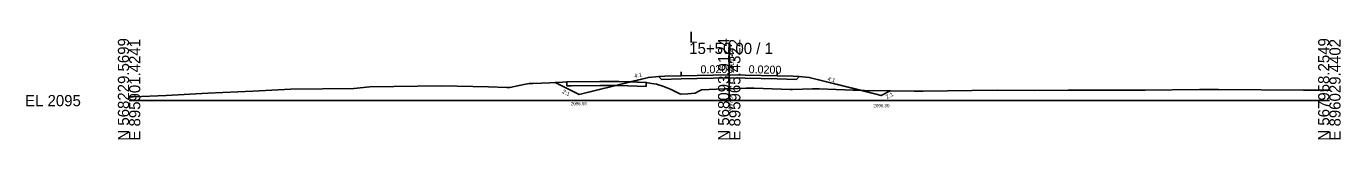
# Model space of a CAD drawing. Extents: x -26 to 1603, y -10 to 13527.
# Drawn here: x -25.7 to 302.8, y 2990.3 to 3017.2 of the extents above; entities that cross this region are included whole.
import ezdxf

# ---------------------------------------------------------------- set-up
doc = ezdxf.new("R2010")
doc.units = 0
for name, color, linetype in [('Default', 7, 'Continuous'), ('Exist XS Center Line Elevation Label', 7, 'Continuous'), ('Exist XS Ground Line', 7, 'Continuous'), ('Old_Level_61', 7, 'Continuous'), ('Old_Level_63', 7, 'Continuous'), ('Prop XS Ditch Slope Text', 7, 'Continuous'), ('Prop XS Ditch Standard Text', 7, 'Continuous'), ('Prop XS Earthwork Shape', 7, 'Continuous'), ('Prop XS EOT Tick Mark', 7, 'Continuous'), ('Prop XS Finish Grade', 7, 'Continuous'), ('Prop XS Finish Grade Earthwork', 7, 'Continuous'), ('Prop XS Finish Grade Paved Shoulder', 7, 'Continuous'), ('Prop XS Finish Grade Pavement', 7, 'Continuous'), ('Prop XS Side Slope Text', 7, 'Continuous'), ('Prop XS Subgrade Earthwork', 7, 'Continuous'), ('Prop XSC Text', 7, 'Continuous')]:
    doc.layers.add(name, color=color, linetype=linetype)

msp = doc.modelspace()

# ---------------------------------------------------------------- linework, layer by layer
at = {"layer": 'Exist XS Ground Line'}
for p, q in [((30.97, 3002.33), (40.4, 3002.86)), ((40.4, 3002.86), (56.16, 3003.06)), ((56.16, 3003.06), (60.17, 3003.41)), ((60.17, 3003.41), (78.12, 3003.66)), ((78.12, 3003.66), (89.84, 3003.44)), ((89.84, 3003.44), (94.43, 3003.24)), ((94.43, 3003.24), (95.17, 3003.27)), ((95.17, 3003.27), (98.7, 3004.04)), ((98.7, 3004.04), (99.98, 3004.25)), ((99.98, 3004.25), (100.92, 3004.31)), ((100.92, 3004.31), (107.37, 3004.53)), ((107.37, 3004.53), (109.45, 3004.66)), ((109.45, 3004.66), (117.69, 3004.76)), ((117.69, 3004.76), (119.89, 3004.81)), ((119.89, 3004.81), (122.45, 3004.77)), ((122.45, 3004.77), (129.28, 3004.56)), ((129.28, 3004.56), (130.61, 3004.28)), ((130.61, 3004.28), (131.86, 3004.14)), ((131.86, 3004.14), (133.43, 3003.65)), ((133.43, 3003.65), (135.52, 3002.74)), ((143.04, 3002.71), (148.74, 3002.93)), ((148.74, 3002.93), (150, 3002.97)), ((150, 3002.97), (154.24, 3003.11)), ((154.24, 3003.11), (156.26, 3003.1)), ((156.26, 3003.1), (165.21, 3002.74)), ((165.84, 3002.76), (170.81, 3002.91)), ((170.81, 3002.91), (172.48, 3002.98)), ((172.48, 3002.98), (181.01, 3002.64)), ((267.55, 3002.76), (271.87, 3002.79)), ((271.87, 3002.79), (272.27, 3002.79)), ((272.27, 3002.79), (293.58, 3002.61)), ((0, 3000.98), (1, 3000.97)), ((1, 3000.97), (9.23, 3001.3)), ((9.23, 3001.3), (19.65, 3001.82)), ((19.65, 3001.82), (30.97, 3002.33)), ((135.52, 3002.74), (137.83, 3001.63)), ((137.83, 3001.63), (139.68, 3001.72)), ((139.68, 3001.72), (141.49, 3001.83)), ((141.49, 3001.83), (142.43, 3002.33)), ((142.43, 3002.33), (143.04, 3002.71)), ((165.21, 3002.74), (165.84, 3002.76)), ((181.01, 3002.64), (183.85, 3002.54)), ((183.85, 3002.54), (196.25, 3002.36)), ((196.25, 3002.36), (196.7, 3002.36)), ((196.7, 3002.36), (197.04, 3002.36)), ((197.04, 3002.36), (198.51, 3002.37)), ((198.51, 3002.37), (210.64, 3002.56)), ((210.64, 3002.56), (217.07, 3002.59)), ((217.07, 3002.59), (226.39, 3002.55)), ((226.39, 3002.55), (234.73, 3002.65)), ((234.73, 3002.65), (235.61, 3002.65)), ((235.61, 3002.65), (250.69, 3002.62)), ((250.69, 3002.62), (253.98, 3002.62)), ((253.98, 3002.62), (267.55, 3002.76)), ((293.58, 3002.61), (300, 3002.58))]:
    msp.add_line(p, q, dxfattribs=at)
at = {"layer": 'Old_Level_61'}
for p, q in [((109.45, 3004.66), (109.45, 3003.66)), ((109.45, 3003.66), (110.47, 3003.68)), ((110.47, 3003.68), (117.69, 3003.76)), ((117.69, 3003.76), (119.89, 3003.81)), ((119.89, 3003.81), (122.45, 3003.77)), ((122.45, 3003.77), (129.28, 3003.56)), ((129.28, 3003.56), (129.28, 3004.56))]:
    msp.add_line(p, q, dxfattribs=at)
at = {"layer": 'Old_Level_63'}
for p, q in [((150, 3000), (150, 3014.44)), ((0, 3000), (150, 3000)), ((150, 3000), (300, 3000))]:
    msp.add_line(p, q, dxfattribs=at)
at = {"layer": 'Prop XS Earthwork Shape'}
for points in [[(106.47, 3004.5), (107.37, 3004.53), (109.45, 3004.66), (117.69, 3004.76), (119.89, 3004.81), (122.45, 3004.77), (125.26, 3004.68), (112.48, 3001.56)], [(162, 3005.41), (166.81, 3005.31), (167.5, 3006), (170, 3005.8), (182.9, 3002.57), (181.01, 3002.64), (172.48, 3002.98), (170.81, 3002.91), (165.84, 3002.76), (165.21, 3002.74), (156.26, 3003.1), (154.24, 3003.11), (150, 3002.97), (148.74, 3002.93), (143.04, 3002.71), (142.43, 3002.33), (141.49, 3001.83), (139.68, 3001.72), (137.83, 3001.63), (135.52, 3002.74), (133.43, 3003.65), (131.86, 3004.14), (130.61, 3004.28), (129.28, 3004.56), (125.26, 3004.68), (129.82, 3005.8), (132.38, 3006), (133.09, 3005.31), (138, 3005.41), (150, 3005.65)], [(183.85, 3002.54), (190.24, 3002.45), (187.96, 3001.31), (182.9, 3002.57)]]:
    msp.add_lwpolyline(points, close=True, dxfattribs=at)
at = {"layer": 'Prop XS EOT Tick Mark'}
for p, q in [((138, 3006.2), (138, 3007.2)), ((162, 3006.2), (162, 3007.2))]:
    msp.add_line(p, q, dxfattribs=at)
at = {"layer": 'Prop XS Finish Grade'}
for p, q in [((133.91, 3006.12), (132.38, 3006)), ((166, 3006.12), (167.5, 3006))]:
    msp.add_line(p, q, dxfattribs=at)
at = {"layer": 'Prop XS Finish Grade Earthwork'}
for p, q in [((112.48, 3001.56), (106.47, 3004.5)), ((129.82, 3005.8), (112.48, 3001.56)), ((132.38, 3006), (129.82, 3005.8)), ((167.5, 3006), (170, 3005.8)), ((170, 3005.8), (187.96, 3001.31)), ((187.96, 3001.31), (190.24, 3002.45))]:
    msp.add_line(p, q, dxfattribs=at)
at = {"layer": 'Prop XS Finish Grade Paved Shoulder'}
for p, q in [((138, 3006.2), (133.91, 3006.12)), ((162, 3006.2), (166, 3006.12))]:
    msp.add_line(p, q, dxfattribs=at)
at = {"layer": 'Prop XS Finish Grade Pavement'}
for p, q in [((138, 3006.2), (150, 3006.44)), ((150, 3006.44), (162, 3006.2))]:
    msp.add_line(p, q, dxfattribs=at)
at = {"layer": 'Prop XS Subgrade Earthwork'}
for p, q in [((133.09, 3005.31), (132.38, 3006)), ((138, 3005.41), (133.09, 3005.31)), ((150, 3005.65), (138, 3005.41)), ((162, 3005.41), (150, 3005.65)), ((162, 3005.41), (166.81, 3005.31)), ((166.81, 3005.31), (167.5, 3006))]:
    msp.add_line(p, q, dxfattribs=at)

# ---------------------------------------------------------------- texts
at = {"layer": 'Default'}
for rotation, p in [(1.1458, (142.84, 3006.79)), (358.8542, (154.84, 3006.85))]:
    msp.add_text('0.0200', height=2, rotation=rotation, dxfattribs=at).set_placement(p)
at = {"layer": 'Exist XS Center Line Elevation Label'}
msp.add_text('2097.97', height=1, rotation=90, dxfattribs=at).set_placement((150.87, 2996.95))
at = {"layer": 'Old_Level_63'}
for s, p in [('L', (140, 3014.44)), ('15+50.00 / 1', (140, 3011.64)), ('EL 2095', (-26, 2998.6))]:
    msp.add_text(s, height=2.8, dxfattribs=at).set_placement(p)
for s, p in [('N 568229.5699', (0, 2990)), ('E 895901.4241', (2.8, 2990)), ('N 568093.9124', (150, 2990)), ('E 895965.4322', (152.8, 2990)), ('N 567958.2549', (300, 2990)), ('E 896029.4402', (302.8, 2990))]:
    msp.add_text(s, height=2.8, rotation=90, dxfattribs=at).set_placement(p)
at = {"layer": 'Prop XS Ditch Slope Text'}
for rotation, p in [(13.7424, (126.41, 3005.6)), (345.9638, (174.52, 3005))]:
    msp.add_text('4:1', height=1, rotation=rotation, dxfattribs=at).set_placement(p)
at = {"layer": 'Prop XS Ditch Standard Text'}
for s, p in [('2096.56', (110.41, 2998.85)), ('2096.30', (186.05, 2998.33))]:
    msp.add_text(s, height=0.8, dxfattribs=at).set_placement(p)
at = {"layer": 'Prop XS Side Slope Text'}
for rotation, p in [(333.936, (108.16, 3001.94)), (26.5651, (189.42, 3000.41))]:
    msp.add_text('2:1', height=1, rotation=rotation, dxfattribs=at).set_placement(p)
at = {"layer": 'Prop XSC Text'}
msp.add_text(' 2101.44', height=1.2, rotation=90, dxfattribs=at).set_placement((151.2, 3006.44))

doc.saveas('drawing.dxf')
